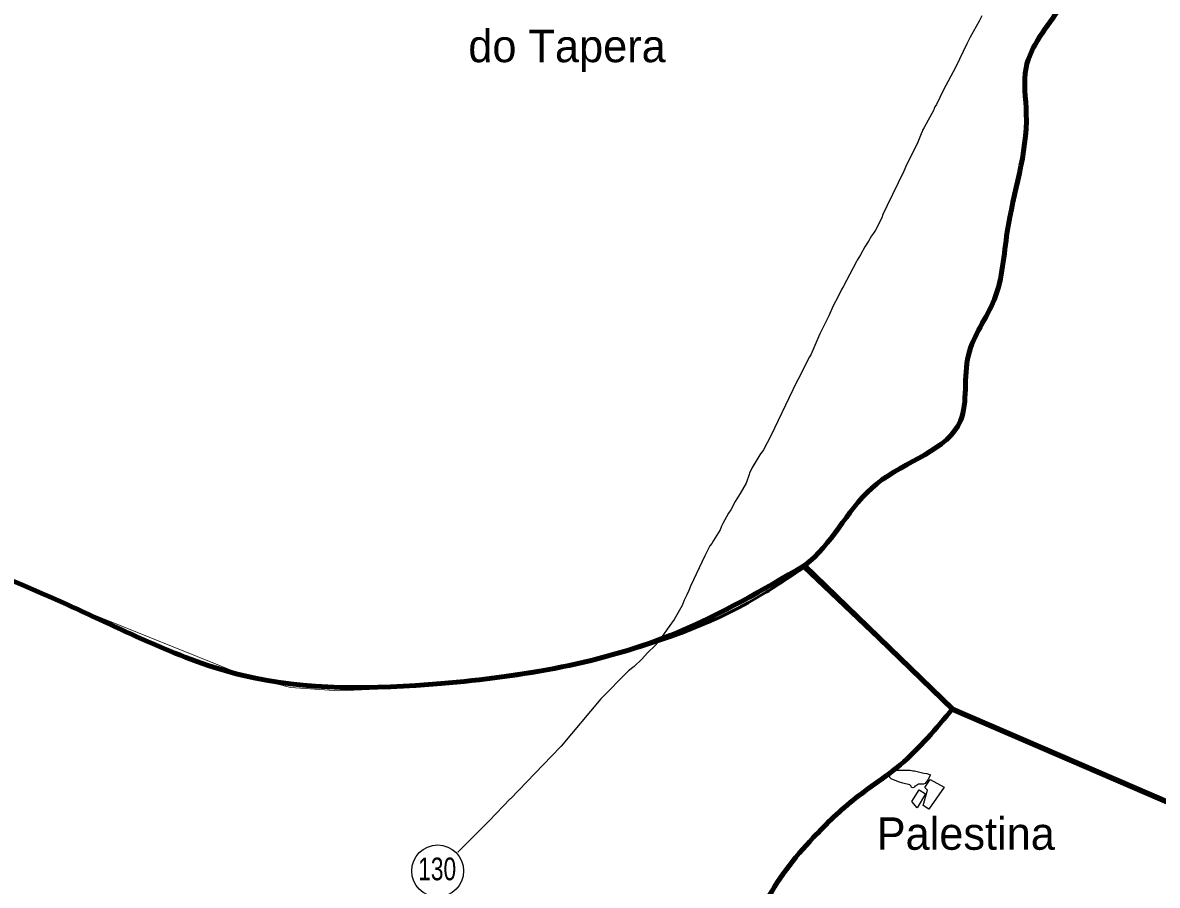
# Model space of a CAD drawing. Extents: x -1643653 to 4543381, y 1624270 to 13878484.
# Drawn here: x 669599 to 687117, y 8928718 to 8942036 of the extents above; entities that cross this region are included whole.
import ezdxf
from ezdxf.enums import TextEntityAlignment as Align

# ---------------------------------------------------------------- set-up
doc = ezdxf.new("R2010")
doc.units = 0
doc.header["$LTSCALE"] = 200
for name, color, linetype, lineweight in [('12', 7, 'Continuous', 25), ('21', 7, 'Continuous', 25), ('23', 7, 'Continuous', 13), ('28', 7, 'Continuous', 53), ('48', 7, 'Continuous', 25), ('60', 7, 'Continuous', 13), ('9', 7, 'Continuous', 90)]:
    doc.layers.add(name, color=color, linetype=linetype, lineweight=lineweight)
doc.layers.add('41', color=7, linetype='Continuous')

msp = doc.modelspace()

# ---------------------------------------------------------------- linework, layer by layer
at = {"layer": '12'}
for points in [[(684406.6, 8942143.9), (684365.6, 8942058.6), (684226.8, 8941813.7), (684226.8, 8941813.7), (684175, 8941710.1)], [(684175, 8941710.1), (684006.3, 8941354.9), (683811.8, 8940990.8), (683708.9, 8940774.6), (683683.4, 8940734.8), (683672.2, 8940709.1)], [(683672.2, 8940709.1), (683664.9, 8940692.3), (683518.7, 8940415.7), (683489.7, 8940375.6), (683483.7, 8940349.2)], [(683483.7, 8940349.2), (683483.6, 8940348.4), (683407.7, 8940165.2), (683245.4, 8939843.2), (683205.2, 8939743.2), (682941, 8939205.2)], [(682941, 8939205.2), (682878.1, 8939077.2), (682861.5, 8939025.1), (682765.5, 8938831.7), (682733.1, 8938786.5)], [(682733.1, 8938786.5), (682705.4, 8938747.7), (682658.5, 8938662.8), (682599.8, 8938576.1), (682535.5, 8938453.1), (682483.4, 8938370.4), (682473, 8938350.6)], [(682473, 8938350.6), (682268.3, 8937959.8), (682239.3, 8937915.4), (682190.6, 8937811.3), (682111.6, 8937663.4), (682046.3, 8937511.5), (681908.7, 8937232.2), (681767.3, 8936909.9), (681749, 8936876)], [(681749, 8936876), (681674.2, 8936737.5), (681598.8, 8936576.5), (681548, 8936488.8), (681147.4, 8935655.4), (681034.1, 8935439.7), (680978.2, 8935363.2), (680858.2, 8935160.4), (680821.2, 8935082.4), (680813.6, 8935058.9)], [(680813.6, 8935058.9), (680770.7, 8934925.3), (680678.2, 8934766.8), (680599.4, 8934646.3), (680530.2, 8934514.3), (680497.2, 8934464.9), (680407.8, 8934301.6), (680390.7, 8934262.8)], [(680390.7, 8934262.8), (680366.4, 8934207.8), (680262.3, 8934041.1), (680239.1, 8933996.7), (680210.5, 8933956.9), (680161.7, 8933865.8)], [(680161.7, 8933865.8), (680129.3, 8933805.3), (679909.7, 8933336.9), (679881.7, 8933269.9)], [(679881.7, 8933269.9), (679854, 8933203.9), (679812.6, 8933121.8), (679778.5, 8933035.9), (679658.3, 8932822.5), (679546.8, 8932670.6), (679434.3, 8932505.7), (679403.8, 8932469.2)], [(679403.8, 8932469.2), (679364.3, 8932422), (679243.8, 8932308), (679157.5, 8932211.5), (679038.6, 8932094.2), (678953.6, 8932030.6), (678525.5, 8931596.9), (677912.2, 8930867.7), (677764.4, 8930713.9), (677128.1, 8930052.4), (677127.3, 8930051.6)], [(677127.3, 8930051.6), (676803, 8929714.4), (676539.8, 8929451), (676316.9, 8929228)]]:
    msp.add_lwpolyline(points, dxfattribs=at)
at = {"layer": '21'}
for points in [[(683365.8, 8930483.5), (683510.5, 8930449.7), (683558.2, 8930444.2), (683616.3, 8930424.2), (683575.5, 8930346.8), (683531.7, 8930288.7), (683504.4, 8930279.3), (683431.3, 8930282), (683384.2, 8930250.7), (683374.9, 8930248.7), (683369.1, 8930234.7), (683343.3, 8930224.6), (683323.7, 8930230), (683316.4, 8930247.3), (683294.6, 8930271.4), (683188.3, 8930293), (683121, 8930313.4), (683006.2, 8930359.9), (682988.3, 8930380), (682982.9, 8930417.6), (683011.5, 8930470.5), (683028.3, 8930482.1), (683057.5, 8930493), (683122.1, 8930496.8), (683191.3, 8930496.1)], [(683191.3, 8930496.1), (683299.3, 8930495), (683342.3, 8930487.2), (683365.8, 8930483.5)]]:
    msp.add_lwpolyline(points, dxfattribs=at)
for points in [[(683526.5, 8930229.3), (683607.8, 8930349.4), (683826.7, 8930234.4), (683590.2, 8929894.4), (683503.7, 8929948.1), (683567.2, 8930185.8)], [(683437.4, 8930190.9), (683536.7, 8930129.6), (683409.5, 8929914.8), (683325.5, 8930009.4)]]:
    msp.add_lwpolyline(points, close=True, dxfattribs=at)
at = {"layer": '23'}
msp.add_lwpolyline([(661559, 8940382.7), (662654, 8939711.5), (668185.2, 8933902.6), (673033, 8931953.6), (673737.6, 8931774.2), (674478.1, 8931718.6), (675299.8, 8931756.9), (675817, 8931812.6), (676417.6, 8931889.3), (676997, 8931967.3), (677379.4, 8932023.7), (677920.8, 8932114.2), (678424.8, 8932214.1), (679006.5, 8932354.8), (679651.8, 8932553.5), (680318.4, 8932822.7), (680715, 8933023.8), (681643.2, 8933612.7), (683955, 8931418.7), (689144, 8929202.5)], dxfattribs=at)
msp.add_lwpolyline([(661559, 8940382.7), (662654, 8939711.5), (668185.2, 8933902.6), (673033, 8931953.6), (673737.6, 8931774.2), (674478.1, 8931718.6), (675299.8, 8931756.9), (675817, 8931812.6), (676417.6, 8931889.3), (676997, 8931967.3), (677379.4, 8932023.7), (677920.8, 8932114.2), (678424.8, 8932214.1), (679006.5, 8932354.8), (679651.8, 8932553.5), (680318.4, 8932822.7), (680715, 8933023.8), (681643.2, 8933612.7), (683955, 8931418.7), (689144, 8929202.5)], dxfattribs=at)
at = {"layer": '28'}
msp.add_lwpolyline([(681670, 8933630.2), (683955, 8931418.7), (688973.1, 8929251.9), (689144, 8929202.5)], dxfattribs=at)
msp.add_spline([(668185.2, 8933939.4), (670277.1, 8933068.1), (672981.1, 8931973.4), (676061.1, 8931843.3), (681079.4, 8933243.3), (681670, 8933630.2)], degree=3, dxfattribs=at)
at = {"layer": '48'}
msp.add_circle((676006.2, 8928939.6), 401.3, dxfattribs=at)
at = {"layer": '60', "lineweight": 25}
msp.add_spline([(814781, 9009175.5), (814787.2, 9009173.4), (814796.9, 9009173.4), (814799.4, 9009172.4), (814805.1, 9009174.5), (814805.6, 9009176.5), (814811.7, 9009179.5), (814811.7, 9009179.5), (814801.5, 9009181), (814790.7, 9009181.5), (814784.1, 9009183.1), (814777.4, 9009185.1), (814778.4, 9009175.5)], degree=3, dxfattribs=at)
at = {"layer": '9'}
msp.add_lwpolyline([(688969.4, 8929279), (683955, 8931444.8), (681670, 8933656.4)], dxfattribs=at)
for points in [[(637260.6, 8972975.8), (641524.5, 8971056.2), (652526.1, 8965412.7), (653164.3, 8965062.8), (670790.5, 8953770.1), (686194, 8943929.9), (696283.3, 8937647.1)], [(681670, 8933656.4), (681750.3, 8933721.2), (682786.5, 8934918.4), (684078.6, 8935889.6), (684199.9, 8936903.1), (684601.9, 8937766.8), (684799.3, 8938806.1), (685093.9, 8940631), (685089.7, 8941339.8), (685618.5, 8942280.3), (686244, 8943891.1)], [(668185.2, 8933928.8), (670277.1, 8933057.6), (672981.1, 8931962.8), (676061.1, 8931832.8), (679695.5, 8932618), (681670, 8933656.4)], [(681689.3, 8922210.8), (681075.2, 8923117.8), (680840, 8924458.2), (680832.7, 8925926.8), (680750.4, 8927167), (681049, 8928410), (681805.8, 8929453.8), (682463.2, 8930066.4), (683146.5, 8930577.9), (683955, 8931444.8)]]:
    msp.add_spline(points, degree=3, dxfattribs=at)

# ---------------------------------------------------------------- texts
at = {"layer": '41'}
msp.add_text('do Tapera', height=500, dxfattribs=at).set_placement((676479.4, 8941426.7))
msp.add_text('Palestina', height=500, dxfattribs=at).set_placement((684159.7, 8929266.8), align=Align.CENTER)
at = {"layer": '48', "width": 0.75}
msp.add_text('130', height=350, dxfattribs=at).set_placement((675998.5, 8928796.1), align=Align.CENTER)

doc.saveas('drawing.dxf')
